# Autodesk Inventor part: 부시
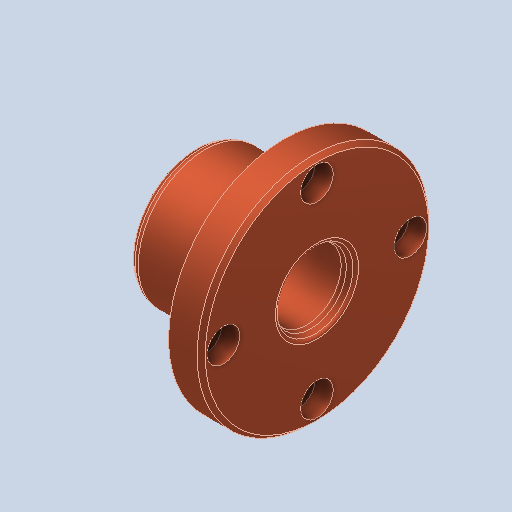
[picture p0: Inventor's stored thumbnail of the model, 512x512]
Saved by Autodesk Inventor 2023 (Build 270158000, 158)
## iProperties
Created: 2024-09
Part Number: 부시
Material: 구리, 합금
Document SubType Name: Modeling
Designer: home
Density: 8.92 g/cm^3
Appearance: 기본값
Author: jhkim
Sending System: Autodesk Inventor 2025
Preprocessor: ST-DEVELOPER v20
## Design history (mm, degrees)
node "부시1"
node "솔리드2"
node "솔리드1"
